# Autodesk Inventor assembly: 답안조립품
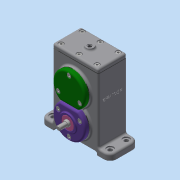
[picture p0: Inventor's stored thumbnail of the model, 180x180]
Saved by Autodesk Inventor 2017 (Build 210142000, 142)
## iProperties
Part Number: 답안조립품
Material: 일반
Document SubType Name: Assembly
Designer: mrc
Author: mrc
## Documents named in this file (24)
- C:\Users\mrc\Desktop\600506V1016\답안조립품.iam
- C:\Users\mrc\Desktop\600506V1016\본체.ipt
- C:\Users\mrc\Desktop\600506V1016\개스킷 A.ipt
- C:\Users\mrc\Desktop\600506V1016\개스킷 B.ipt
- C:\Users\mrc\Desktop\600506V1016\개스킷 C.ipt
- C:\Users\mrc\Desktop\600506V1016\베어링 6001.ipt
- 베어링 6001.ipt
- C:\Users\mrc\Desktop\600506V1016\베어링 6002.ipt
- 베어링 6002.ipt
- C:\Users\mrc\Desktop\600506V1016\볼트 M4.ipt
- C:\Users\mrc\Desktop\600506V1016\스퍼기어 A.ipt
- C:\Users\mrc\Desktop\600506V1016\스퍼기어 B.ipt
- C:\Users\mrc\Desktop\600506V1016\오일 실 10 20 7.ipt
- C:\Users\mrc\Desktop\600506V1016\오일 실 12 22 7.ipt
- C:\Users\mrc\Desktop\600506V1016\축 A.ipt
- C:\Users\mrc\Desktop\600506V1016\축 B.ipt
- C:\Users\mrc\Desktop\600506V1016\칼라.ipt
- C:\Users\mrc\Desktop\600506V1016\커버 A.ipt
- C:\Users\mrc\Desktop\600506V1016\커버 B.ipt
- C:\Users\mrc\Desktop\600506V1016\커버 C.ipt
- C:\Users\mrc\Desktop\600506V1016\커버 D.ipt
- C:\Users\mrc\Desktop\600506V1016\커버 E.ipt
- C:\Users\mrc\Desktop\600506V1016\키 4 x 4 x 12.ipt
- C:\Users\mrc\Desktop\600506V1016\키 5 x 5 x 12.ipt
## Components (5 placed, 3 different names)
1. 개스킷 A:1
2. 개스킷 B:1
3. 개스킷 C:1
4. 개스킷 B:2
5. 개스킷 A:2
